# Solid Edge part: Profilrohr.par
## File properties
Username: bmolnar
Dokumentum tartalom típus: 0
Author: bmolnar
Last saved by: bmolnar
Revision: 87
Sűrűség: 0,000 kg/m^3
Pontosság: 0,990
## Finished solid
Body 1: solid body, 115 faces, 338 edges, 224 vertices.
  Faces by surface: cylinder 59, plane 56
  Edges by curve: line 220, circle 118
Bounding box of the edges (mm): 77.000 x 77.000 x 101.500, from (-38.5, -38.5, 0) to (38.5, 38.5, 101.5).
Cylindrical faces by radius (mm): R0.15 x24, R0.25 x24, R1 x4, R12 x4, R13.5 x2, R31.5 x1
Planar faces by outward normal: +x 13, +y 14, +z 1, -x 13, -y 14, -z 1
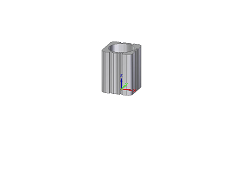
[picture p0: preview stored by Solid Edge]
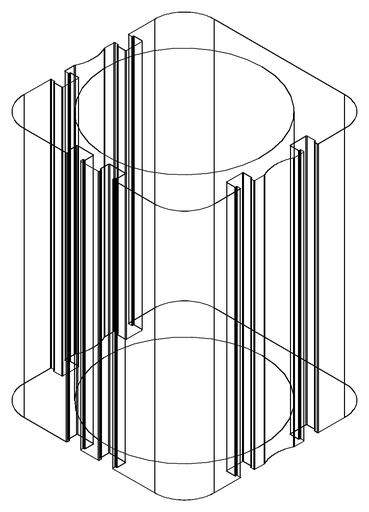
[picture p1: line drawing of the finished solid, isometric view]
